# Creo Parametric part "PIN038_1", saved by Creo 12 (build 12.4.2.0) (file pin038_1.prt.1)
Units: Custom; MM, KILOGRAM, SECS

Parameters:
  PTC_WM_ITERATION = "0"
  PTC_WM_VERSION = "-.0"
  PTC_WM_LIFECYCLE_STATE = "In Work"
  PTC_WM_LIFECYCLE = "MO_CADDocument"
  PTC_WM_CREATED_BY = "Maximilian Roepper (Z0017RMS: MO)"
  PTC_WM_CREATED_ON = "18-Sep-26 11:36:42 AM"
  PTC_WM_MODIFIED_BY = "Maximilian Roepper (Z0017RMS: MO)"
  PTC_WM_MODIFIED_ON = "18-Sep-26 11:36:46 AM"
  PDMLINKNUMBER = "PDM000071455282"
  PTC_WM_NAME = "pin038_1.prt"
  PTC_WM_NUMBER = "PDM000071455282"

Other parameters: WEIGHT, WEIGHT_FACTOR, WEIGHT_ADD, _MASS_TEMP, _DIFF_TEMP, MC_ERRORS, SUPPLIER

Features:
  1. coordinate system
  2. datum plane "PRT_YZ"
  3. datum plane "PRT_XY"
  4. datum plane "PRT_XZ"
  5. coordinate system
  6. datum axis
  7. datum axis
  8. datum axis
  9. coordinate system
  10. imported feature

Other named items: PRT, SIEMENS_MO, DRW_VIEW_ORG, PRT_X, PRT_Y, PRT_Z, CS0, ROUGH_GROB

Layers: 00_STD_CSYS-KSYS, 01_STD_PLANES-EBENEN, 02_STD_AXES-ACHSEN, 03_STD_CSYS-KSYS, 24_IMPORT_FEAT-IMPORT_KE

Surfaces: 10 plane, 4 cylinder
